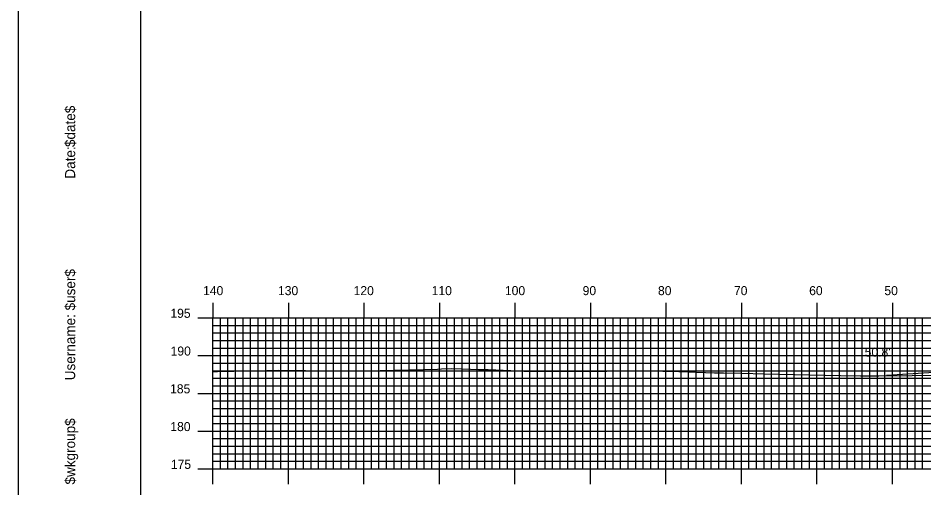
# Model space of a CAD drawing. Extents: x 1825147 to 1825490, y 442591 to 442811.
# Drawn here: x 1825146.6 to 1825266.5, y 442686.2 to 442748.4 of the extents above; entities that cross this region are included whole.
import ezdxf

# ---------------------------------------------------------------- set-up
doc = ezdxf.new("R2010")
doc.units = 0
for name, color, linetype in [('BORDER', 7, 'Continuous'), ('D_Roadway_SubGrade', 7, 'Continuous'), ('D_Text_Standard', 7, 'Continuous'), ('H_V ANNOTATION', 7, 'Continuous'), ('MAJOR', 7, 'Continuous'), ('MINOR', 7, 'Continuous'), ('PLOT BOUNDARY', 7, 'Continuous'), ('S_Roadway_Centerline', 7, 'Continuous')]:
    doc.layers.add(name, color=color, linetype=linetype)

msp = doc.modelspace()

# ---------------------------------------------------------------- linework, layer by layer
at = {"layer": 'BORDER'}
msp.add_lwpolyline([(1825162.76, 442596.67), (1825482.76, 442596.67), (1825482.76, 442806.67), (1825162.76, 442806.67)], close=True, dxfattribs=at)
at = {"layer": 'D_Roadway_SubGrade'}
msp.add_line((1825280.36, 442702.21), (1825261.59, 442701.02), dxfattribs=at)
at = {"layer": 'MAJOR'}
for p, q in [((1825172.36, 442710.67), (1825172.36, 442708.67)), ((1825182.36, 442710.67), (1825182.36, 442708.67)), ((1825192.36, 442710.67), (1825192.36, 442708.67)), ((1825202.36, 442710.67), (1825202.36, 442708.67)), ((1825212.36, 442710.67), (1825212.36, 442708.67)), ((1825222.36, 442710.67), (1825222.36, 442708.67)), ((1825232.36, 442710.67), (1825232.36, 442708.67)), ((1825242.36, 442710.67), (1825242.36, 442708.67)), ((1825252.36, 442710.67), (1825252.36, 442708.67)), ((1825262.36, 442710.67), (1825262.36, 442708.67)), ((1825170.36, 442708.67), (1825172.36, 442708.67)), ((1825172.36, 442708.67), (1825452.36, 442708.67)), ((1825172.36, 442688.67), (1825172.36, 442708.67)), ((1825172.36, 442708.67), (1825452.36, 442708.67)), ((1825172.36, 442688.67), (1825172.36, 442708.67)), ((1825172.36, 442688.67), (1825172.36, 442708.67)), ((1825172.36, 442708.67), (1825452.36, 442708.67)), ((1825182.36, 442688.67), (1825182.36, 442708.67)), ((1825182.36, 442688.67), (1825182.36, 442708.67)), ((1825192.36, 442688.67), (1825192.36, 442708.67)), ((1825192.36, 442688.67), (1825192.36, 442708.67)), ((1825202.36, 442688.67), (1825202.36, 442708.67)), ((1825202.36, 442688.67), (1825202.36, 442708.67)), ((1825212.36, 442688.67), (1825212.36, 442708.67)), ((1825212.36, 442688.67), (1825212.36, 442708.67)), ((1825222.36, 442688.67), (1825222.36, 442708.67)), ((1825222.36, 442688.67), (1825222.36, 442708.67)), ((1825232.36, 442688.67), (1825232.36, 442708.67)), ((1825232.36, 442688.67), (1825232.36, 442708.67)), ((1825242.36, 442688.67), (1825242.36, 442708.67)), ((1825242.36, 442688.67), (1825242.36, 442708.67)), ((1825252.36, 442688.67), (1825252.36, 442708.67)), ((1825252.36, 442688.67), (1825252.36, 442708.67)), ((1825262.36, 442688.67), (1825262.36, 442708.67)), ((1825262.36, 442688.67), (1825262.36, 442708.67)), ((1825170.36, 442703.67), (1825172.36, 442703.67)), ((1825172.36, 442703.67), (1825452.36, 442703.67)), ((1825172.36, 442703.67), (1825452.36, 442703.67)), ((1825170.36, 442698.67), (1825172.36, 442698.67)), ((1825172.36, 442698.67), (1825452.36, 442698.67)), ((1825172.36, 442698.67), (1825452.36, 442698.67)), ((1825170.36, 442693.67), (1825172.36, 442693.67)), ((1825172.36, 442693.67), (1825452.36, 442693.67)), ((1825172.36, 442693.67), (1825452.36, 442693.67)), ((1825170.36, 442688.67), (1825172.36, 442688.67)), ((1825172.36, 442688.67), (1825452.36, 442688.67)), ((1825172.36, 442688.67), (1825452.36, 442688.67)), ((1825172.36, 442688.67), (1825452.36, 442688.67)), ((1825172.36, 442686.66), (1825172.36, 442688.67)), ((1825182.36, 442686.66), (1825182.36, 442688.67)), ((1825192.36, 442686.66), (1825192.36, 442688.67)), ((1825202.36, 442686.66), (1825202.36, 442688.67)), ((1825212.36, 442686.66), (1825212.36, 442688.67)), ((1825222.36, 442686.66), (1825222.36, 442688.67)), ((1825232.36, 442686.66), (1825232.36, 442688.67)), ((1825242.36, 442686.66), (1825242.36, 442688.67)), ((1825252.36, 442686.66), (1825252.36, 442688.67)), ((1825262.36, 442686.66), (1825262.36, 442688.67))]:
    msp.add_line(p, q, dxfattribs=at)
at = {"layer": 'MINOR'}
for p, q in [((1825173.36, 442688.67), (1825173.36, 442708.67)), ((1825173.36, 442688.67), (1825173.36, 442708.67)), ((1825174.36, 442688.67), (1825174.36, 442708.67)), ((1825174.36, 442688.67), (1825174.36, 442708.67)), ((1825175.36, 442688.67), (1825175.36, 442708.67)), ((1825175.36, 442688.67), (1825175.36, 442708.67)), ((1825176.36, 442688.67), (1825176.36, 442708.67)), ((1825176.36, 442688.67), (1825176.36, 442708.67)), ((1825177.36, 442688.67), (1825177.36, 442708.67)), ((1825177.36, 442688.67), (1825177.36, 442708.67)), ((1825178.36, 442688.67), (1825178.36, 442708.67)), ((1825178.36, 442688.67), (1825178.36, 442708.67)), ((1825179.36, 442688.67), (1825179.36, 442708.67)), ((1825179.36, 442688.67), (1825179.36, 442708.67)), ((1825180.36, 442688.67), (1825180.36, 442708.67)), ((1825180.36, 442688.67), (1825180.36, 442708.67)), ((1825181.36, 442688.67), (1825181.36, 442708.67)), ((1825181.36, 442688.67), (1825181.36, 442708.67)), ((1825183.36, 442688.67), (1825183.36, 442708.67)), ((1825183.36, 442688.67), (1825183.36, 442708.67)), ((1825184.36, 442688.67), (1825184.36, 442708.67)), ((1825184.36, 442688.67), (1825184.36, 442708.67)), ((1825185.36, 442688.67), (1825185.36, 442708.67)), ((1825185.36, 442688.67), (1825185.36, 442708.67)), ((1825186.36, 442688.67), (1825186.36, 442708.67)), ((1825186.36, 442688.67), (1825186.36, 442708.67)), ((1825187.36, 442688.67), (1825187.36, 442708.67)), ((1825187.36, 442688.67), (1825187.36, 442708.67)), ((1825188.36, 442688.67), (1825188.36, 442708.67)), ((1825188.36, 442688.67), (1825188.36, 442708.67)), ((1825189.36, 442688.67), (1825189.36, 442708.67)), ((1825189.36, 442688.67), (1825189.36, 442708.67)), ((1825190.36, 442688.67), (1825190.36, 442708.67)), ((1825190.36, 442688.67), (1825190.36, 442708.67)), ((1825191.36, 442688.67), (1825191.36, 442708.67)), ((1825191.36, 442688.67), (1825191.36, 442708.67)), ((1825193.36, 442688.67), (1825193.36, 442708.67)), ((1825193.36, 442688.67), (1825193.36, 442708.67)), ((1825194.36, 442688.67), (1825194.36, 442708.67)), ((1825194.36, 442688.67), (1825194.36, 442708.67)), ((1825195.36, 442688.67), (1825195.36, 442708.67)), ((1825195.36, 442688.67), (1825195.36, 442708.67)), ((1825196.36, 442688.67), (1825196.36, 442708.67)), ((1825196.36, 442688.67), (1825196.36, 442708.67)), ((1825197.36, 442688.67), (1825197.36, 442708.67)), ((1825197.36, 442688.67), (1825197.36, 442708.67)), ((1825198.36, 442688.67), (1825198.36, 442708.67)), ((1825198.36, 442688.67), (1825198.36, 442708.67)), ((1825199.36, 442688.67), (1825199.36, 442708.67)), ((1825199.36, 442688.67), (1825199.36, 442708.67)), ((1825200.36, 442688.67), (1825200.36, 442708.67)), ((1825200.36, 442688.67), (1825200.36, 442708.67)), ((1825201.36, 442688.67), (1825201.36, 442708.67)), ((1825201.36, 442688.67), (1825201.36, 442708.67)), ((1825203.36, 442688.67), (1825203.36, 442708.67)), ((1825203.36, 442688.67), (1825203.36, 442708.67)), ((1825204.36, 442688.67), (1825204.36, 442708.67)), ((1825204.36, 442688.67), (1825204.36, 442708.67)), ((1825205.36, 442688.67), (1825205.36, 442708.67)), ((1825205.36, 442688.67), (1825205.36, 442708.67)), ((1825206.36, 442688.67), (1825206.36, 442708.67)), ((1825206.36, 442688.67), (1825206.36, 442708.67)), ((1825207.36, 442688.67), (1825207.36, 442708.67)), ((1825207.36, 442688.67), (1825207.36, 442708.67)), ((1825208.36, 442688.67), (1825208.36, 442708.67)), ((1825208.36, 442688.67), (1825208.36, 442708.67)), ((1825209.36, 442688.67), (1825209.36, 442708.67)), ((1825209.36, 442688.67), (1825209.36, 442708.67)), ((1825210.36, 442688.67), (1825210.36, 442708.67)), ((1825210.36, 442688.67), (1825210.36, 442708.67)), ((1825211.36, 442688.67), (1825211.36, 442708.67)), ((1825211.36, 442688.67), (1825211.36, 442708.67)), ((1825213.36, 442688.67), (1825213.36, 442708.67)), ((1825213.36, 442688.67), (1825213.36, 442708.67)), ((1825214.36, 442688.67), (1825214.36, 442708.67)), ((1825214.36, 442688.67), (1825214.36, 442708.67)), ((1825215.36, 442688.67), (1825215.36, 442708.67)), ((1825215.36, 442688.67), (1825215.36, 442708.67)), ((1825216.36, 442688.67), (1825216.36, 442708.67)), ((1825216.36, 442688.67), (1825216.36, 442708.67)), ((1825217.36, 442688.67), (1825217.36, 442708.67)), ((1825217.36, 442688.67), (1825217.36, 442708.67)), ((1825218.36, 442688.67), (1825218.36, 442708.67)), ((1825218.36, 442688.67), (1825218.36, 442708.67)), ((1825219.36, 442688.67), (1825219.36, 442708.67)), ((1825219.36, 442688.67), (1825219.36, 442708.67)), ((1825220.36, 442688.67), (1825220.36, 442708.67)), ((1825220.36, 442688.67), (1825220.36, 442708.67)), ((1825221.36, 442688.67), (1825221.36, 442708.67)), ((1825221.36, 442688.67), (1825221.36, 442708.67)), ((1825223.36, 442688.67), (1825223.36, 442708.67)), ((1825223.36, 442688.67), (1825223.36, 442708.67)), ((1825224.36, 442688.67), (1825224.36, 442708.67)), ((1825224.36, 442688.67), (1825224.36, 442708.67)), ((1825225.36, 442688.67), (1825225.36, 442708.67)), ((1825225.36, 442688.67), (1825225.36, 442708.67)), ((1825226.36, 442688.67), (1825226.36, 442708.67)), ((1825226.36, 442688.67), (1825226.36, 442708.67)), ((1825227.36, 442688.67), (1825227.36, 442708.67)), ((1825227.36, 442688.67), (1825227.36, 442708.67)), ((1825228.36, 442688.67), (1825228.36, 442708.67)), ((1825228.36, 442688.67), (1825228.36, 442708.67)), ((1825229.36, 442688.67), (1825229.36, 442708.67)), ((1825229.36, 442688.67), (1825229.36, 442708.67)), ((1825230.36, 442688.67), (1825230.36, 442708.67)), ((1825230.36, 442688.67), (1825230.36, 442708.67)), ((1825231.36, 442688.67), (1825231.36, 442708.67)), ((1825231.36, 442688.67), (1825231.36, 442708.67)), ((1825233.36, 442688.67), (1825233.36, 442708.67)), ((1825233.36, 442688.67), (1825233.36, 442708.67)), ((1825234.36, 442688.67), (1825234.36, 442708.67)), ((1825234.36, 442688.67), (1825234.36, 442708.67)), ((1825235.36, 442688.67), (1825235.36, 442708.67)), ((1825235.36, 442688.67), (1825235.36, 442708.67)), ((1825236.36, 442688.67), (1825236.36, 442708.67)), ((1825236.36, 442688.67), (1825236.36, 442708.67)), ((1825237.36, 442688.67), (1825237.36, 442708.67)), ((1825237.36, 442688.67), (1825237.36, 442708.67)), ((1825238.36, 442688.67), (1825238.36, 442708.67)), ((1825238.36, 442688.67), (1825238.36, 442708.67)), ((1825239.36, 442688.67), (1825239.36, 442708.67)), ((1825239.36, 442688.67), (1825239.36, 442708.67)), ((1825240.36, 442688.67), (1825240.36, 442708.67)), ((1825240.36, 442688.67), (1825240.36, 442708.67)), ((1825241.36, 442688.67), (1825241.36, 442708.67)), ((1825241.36, 442688.67), (1825241.36, 442708.67)), ((1825243.36, 442688.67), (1825243.36, 442708.67)), ((1825243.36, 442688.67), (1825243.36, 442708.67)), ((1825244.36, 442688.67), (1825244.36, 442708.67)), ((1825244.36, 442688.67), (1825244.36, 442708.67)), ((1825245.36, 442688.67), (1825245.36, 442708.67)), ((1825245.36, 442688.67), (1825245.36, 442708.67)), ((1825246.36, 442688.67), (1825246.36, 442708.67)), ((1825246.36, 442688.67), (1825246.36, 442708.67)), ((1825247.36, 442688.67), (1825247.36, 442708.67)), ((1825247.36, 442688.67), (1825247.36, 442708.67)), ((1825248.36, 442688.67), (1825248.36, 442708.67)), ((1825248.36, 442688.67), (1825248.36, 442708.67)), ((1825249.36, 442688.67), (1825249.36, 442708.67)), ((1825249.36, 442688.67), (1825249.36, 442708.67)), ((1825250.36, 442688.67), (1825250.36, 442708.67)), ((1825250.36, 442688.67), (1825250.36, 442708.67)), ((1825251.36, 442688.67), (1825251.36, 442708.67)), ((1825251.36, 442688.67), (1825251.36, 442708.67)), ((1825253.36, 442688.67), (1825253.36, 442708.67)), ((1825253.36, 442688.67), (1825253.36, 442708.67)), ((1825254.36, 442688.67), (1825254.36, 442708.67)), ((1825254.36, 442688.67), (1825254.36, 442708.67)), ((1825255.36, 442688.67), (1825255.36, 442708.67)), ((1825255.36, 442688.67), (1825255.36, 442708.67)), ((1825256.36, 442688.67), (1825256.36, 442708.67)), ((1825256.36, 442688.67), (1825256.36, 442708.67)), ((1825257.36, 442688.67), (1825257.36, 442708.67)), ((1825257.36, 442688.67), (1825257.36, 442708.67)), ((1825258.36, 442688.67), (1825258.36, 442708.67)), ((1825258.36, 442688.67), (1825258.36, 442708.67)), ((1825259.36, 442688.67), (1825259.36, 442708.67)), ((1825259.36, 442688.67), (1825259.36, 442708.67)), ((1825260.36, 442688.67), (1825260.36, 442708.67)), ((1825260.36, 442688.67), (1825260.36, 442708.67)), ((1825261.36, 442688.67), (1825261.36, 442708.67)), ((1825261.36, 442688.67), (1825261.36, 442708.67)), ((1825263.36, 442688.67), (1825263.36, 442708.67)), ((1825263.36, 442688.67), (1825263.36, 442708.67)), ((1825264.36, 442688.67), (1825264.36, 442708.67)), ((1825264.36, 442688.67), (1825264.36, 442708.67)), ((1825265.36, 442688.67), (1825265.36, 442708.67)), ((1825265.36, 442688.67), (1825265.36, 442708.67)), ((1825266.36, 442688.67), (1825266.36, 442708.67)), ((1825266.36, 442688.67), (1825266.36, 442708.67)), ((1825172.36, 442707.67), (1825452.36, 442707.67)), ((1825172.36, 442707.67), (1825452.36, 442707.67)), ((1825172.36, 442707.67), (1825174.37, 442707.67)), ((1825172.36, 442706.67), (1825452.36, 442706.67)), ((1825172.36, 442706.67), (1825452.36, 442706.67)), ((1825172.36, 442706.67), (1825174.37, 442706.67)), ((1825172.36, 442705.67), (1825452.36, 442705.67)), ((1825172.36, 442705.67), (1825452.36, 442705.67)), ((1825172.36, 442705.67), (1825174.37, 442705.67)), ((1825172.36, 442704.67), (1825452.36, 442704.67)), ((1825172.36, 442704.67), (1825452.36, 442704.67)), ((1825172.36, 442704.67), (1825174.37, 442704.67)), ((1825172.36, 442702.67), (1825452.36, 442702.67)), ((1825172.36, 442702.67), (1825452.36, 442702.67)), ((1825172.36, 442702.67), (1825174.37, 442702.67)), ((1825172.36, 442701.67), (1825452.36, 442701.67)), ((1825172.36, 442701.67), (1825452.36, 442701.67)), ((1825172.36, 442701.67), (1825174.37, 442701.67)), ((1825172.36, 442700.67), (1825452.36, 442700.67)), ((1825172.36, 442700.67), (1825452.36, 442700.67)), ((1825172.36, 442700.67), (1825174.37, 442700.67)), ((1825172.36, 442699.67), (1825452.36, 442699.67)), ((1825172.36, 442699.67), (1825452.36, 442699.67)), ((1825172.36, 442699.67), (1825174.37, 442699.67)), ((1825172.36, 442697.67), (1825452.36, 442697.67)), ((1825172.36, 442697.67), (1825452.36, 442697.67)), ((1825172.36, 442697.67), (1825174.37, 442697.67)), ((1825172.36, 442696.67), (1825452.36, 442696.67)), ((1825172.36, 442696.67), (1825452.36, 442696.67)), ((1825172.36, 442696.67), (1825174.37, 442696.67)), ((1825172.36, 442695.67), (1825452.36, 442695.67)), ((1825172.36, 442695.67), (1825452.36, 442695.67)), ((1825172.36, 442695.67), (1825174.37, 442695.67)), ((1825172.36, 442694.67), (1825452.36, 442694.67)), ((1825172.36, 442694.67), (1825452.36, 442694.67)), ((1825172.36, 442694.67), (1825174.37, 442694.67)), ((1825172.36, 442692.67), (1825452.36, 442692.67)), ((1825172.36, 442692.67), (1825452.36, 442692.67)), ((1825172.36, 442692.67), (1825174.37, 442692.67)), ((1825172.36, 442691.67), (1825452.36, 442691.67)), ((1825172.36, 442691.67), (1825452.36, 442691.67)), ((1825172.36, 442691.67), (1825174.37, 442691.67)), ((1825172.36, 442690.67), (1825452.36, 442690.67)), ((1825172.36, 442690.67), (1825452.36, 442690.67)), ((1825172.36, 442690.67), (1825174.37, 442690.67)), ((1825172.36, 442689.67), (1825452.36, 442689.67)), ((1825172.36, 442689.67), (1825452.36, 442689.67)), ((1825172.36, 442689.67), (1825174.37, 442689.67))]:
    msp.add_line(p, q, dxfattribs=at)
at = {"layer": 'PLOT BOUNDARY'}
msp.add_lwpolyline([(1825146.57, 442590.55), (1825486.57, 442590.55), (1825486.57, 442810.55), (1825146.57, 442810.55)], close=True, dxfattribs=at)
at = {"layer": 'S_Roadway_Centerline'}
msp.add_lwpolyline([(1825172.36, 442701.54), (1825172.99, 442701.55), (1825179.51, 442701.69), (1825180.48, 442701.69), (1825181.04, 442701.72), (1825188.2, 442701.64), (1825192.6, 442701.67), (1825202.12, 442701.89), (1825202.65, 442701.92), (1825203.93, 442701.96), (1825205.32, 442701.9), (1825206.47, 442701.86), (1825207.55, 442701.81), (1825208.84, 442701.81), (1825212.83, 442701.64), (1825213.56, 442701.62), (1825216.75, 442701.61), (1825219.48, 442701.62), (1825222.19, 442701.58), (1825226.9, 442701.66), (1825231.64, 442701.63), (1825231.93, 442701.62), (1825232.86, 442701.59), (1825238.79, 442701.38), (1825240, 442701.37), (1825242.4, 442701.33), (1825245.38, 442701.24), (1825255.47, 442701.02), (1825258.14, 442701.01), (1825260.56, 442701.01), (1825273.77, 442701.13)], dxfattribs=at)

# ---------------------------------------------------------------- texts
at = {"layer": 'BORDER'}
for s, p in [('$date$', (1825154.13, 442731.28)), ('Date:', (1825154.13, 442727.1)), ('$user$', (1825154.13, 442709.65)), ('Username:', (1825154.13, 442700.4)), ('$wkgroup$', (1825154.13, 442686.6))]:
    msp.add_text(s, height=1.339, rotation=90, dxfattribs=at).set_placement(p)
at = {"layer": 'D_Text_Standard'}
msp.add_text("50.8'", height=1.2, dxfattribs=at).set_placement((1825258.68, 442703.53))
at = {"layer": 'H_V ANNOTATION'}
for s, p in [('140', (1825171.07, 442711.67)), ('130', (1825180.99, 442711.67)), ('120', (1825191, 442711.67)), ('110', (1825201.34, 442711.67)), ('100', (1825211.04, 442711.67)), ('90', (1825221.33, 442711.67)), ('80', (1825231.31, 442711.67)), ('70', (1825241.37, 442711.67)), ('60', (1825251.33, 442711.67)), ('50', (1825261.29, 442711.67)), ('195', (1825166.74, 442708.67)), ('190', (1825166.77, 442703.67)), ('185', (1825166.7, 442698.67)), ('180', (1825166.73, 442693.67)), ('175', (1825166.8, 442688.67))]:
    msp.add_text(s, height=1.2, dxfattribs=at).set_placement(p)
at = {"layer": 'MAJOR'}
msp.add_text('-', height=0.012, dxfattribs=at).set_placement((1825172.35, 442688.67))

doc.saveas('drawing.dxf')
